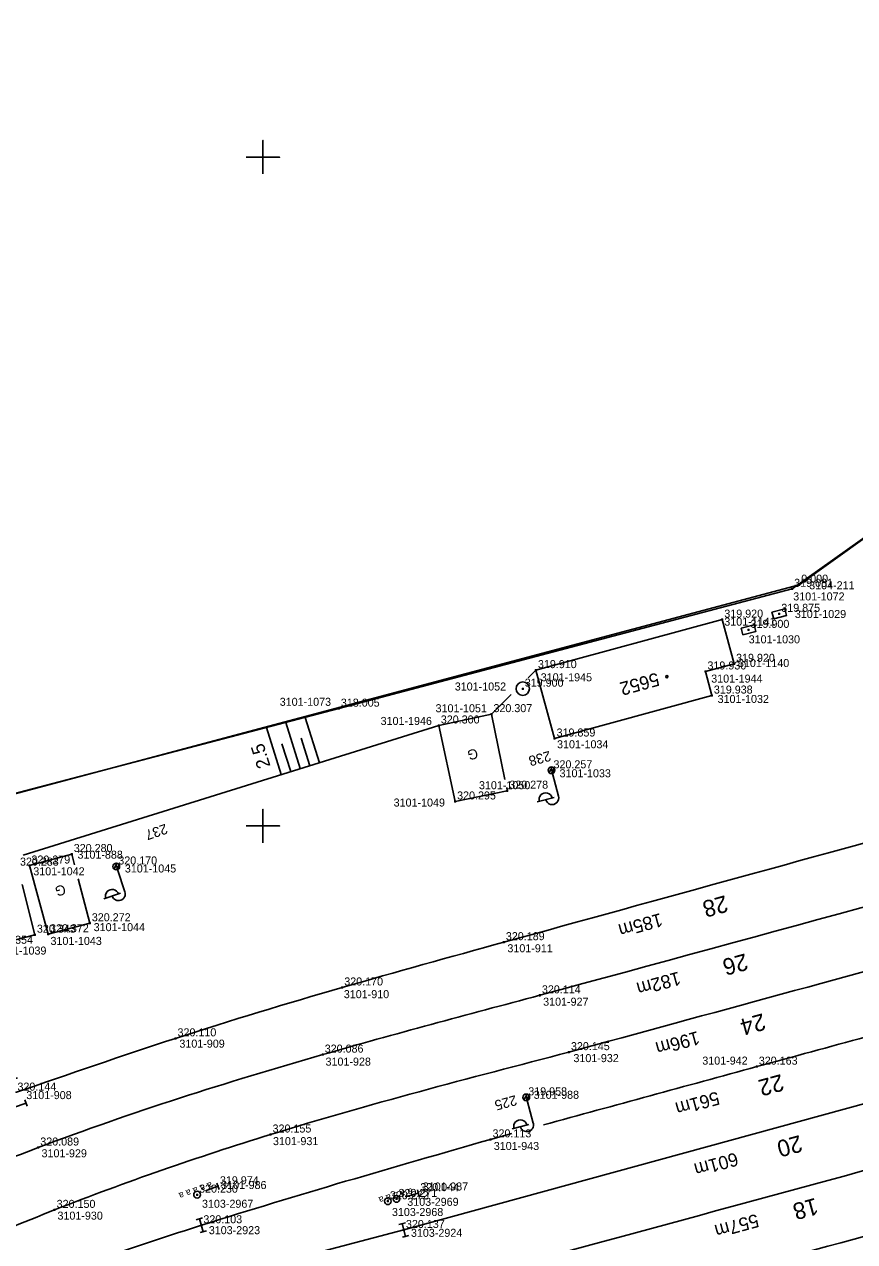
# Model space of a CAD drawing. Extents: x -821875 to -821475, y -1070280 to -1069975.
# Drawn here: x -821717.8 to -821655.7, y -1070181.1 to -1070090.1 of the extents above; entities that cross this region are included whole.
import ezdxf

# ---------------------------------------------------------------- set-up
doc = ezdxf.new("R2010")
doc.units = 0
for name, color, linetype in [('Vrstva 1', 7, 'Continuous'), ('Vrstva 15', 7, 'Continuous'), ('Vrstva 17', 7, 'Continuous'), ('Vrstva 23', 7, 'Continuous'), ('Vrstva 25', 7, 'Continuous'), ('Vrstva 28', 7, 'Continuous'), ('Vrstva 3', 7, 'Continuous'), ('Vrstva 43', 7, 'Continuous'), ('Vrstva 48', 7, 'Continuous'), ('Vrstva 49', 7, 'Continuous'), ('Vrstva 52', 7, 'Continuous'), ('Vrstva 53', 7, 'Continuous'), ('Vrstva 57', 7, 'Continuous'), ('Vrstva 59', 7, 'Continuous'), ('Vrstva 6', 7, 'Continuous'), ('Vrstva 60', 7, 'Continuous'), ('Vrstva 61', 7, 'Continuous')]:
    doc.layers.add(name, color=color, linetype=linetype)

# ---------------------------------------------------------------- blocks, each defined once
blk = doc.blocks.new('BOD')
at = {"layer": 'Vrstva 3'}
for p, q in [((-0.15, 0), (0.15, 0)), ((0, -0.15), (0, 0.15))]:
    blk.add_line(p, q, dxfattribs=at)

msp = doc.modelspace()

# ---------------------------------------------------------------- linework, layer by layer
at = {"layer": 'Vrstva 1'}
for p, q in [((-821682.909, -1070141.641), (-821682.909, -1070141.641)), ((-821681.396, -1070173.002), (-821682.977, -1070173.434))]:
    msp.add_line(p, q, dxfattribs=at)
for points in [[(-821701.25, -1070100), (-821700, -1070100), (-821700, -1070098.75), (-821700, -1070100), (-821698.75, -1070100), (-821700, -1070100), (-821700, -1070101.25)], [(-821701.25, -1070150), (-821700, -1070150), (-821700, -1070148.75), (-821700, -1070150), (-821698.75, -1070150), (-821700, -1070150), (-821700, -1070151.25)], [(-821647.71, -1070168.745), (-821689.454, -1070180.207)], [(-821689.454, -1070180.207), (-821700.898, -1070183.216)]]:
    msp.add_lwpolyline(points, dxfattribs=at)
for points in [[(-821515.135, -1070116.801), (-821528.933, -1070119.148), (-821545.007, -1070122.191), (-821565.452, -1070126.847), (-821593.911, -1070134.524), (-821616.729, -1070140.773), (-821646.681, -1070148.977), (-821681.98, -1070158.691), (-821694.065, -1070162.076), (-821706.535, -1070165.88), (-821718.507, -1070169.937)], [(-821540.596, -1070125.428), (-821552.18, -1070128.307), (-821562.458, -1070130.974), (-821571.2, -1070133.262), (-821591.887, -1070138.848), (-821628.102, -1070148.713), (-821679.285, -1070162.663)], [(-821540.784, -1070127.42), (-821561.358, -1070134.748), (-821573.215, -1070138.464), (-821586.824, -1070142.326), (-821602.341, -1070146.553), (-821645.37, -1070158.257), (-821677.113, -1070166.912)], [(-821500, -1070134.157), (-821525.227, -1070140.424), (-821545.665, -1070145.962), (-821584.89, -1070156.649), (-821608.863, -1070163.173), (-821645.742, -1070173.228), (-821684.141, -1070183.689)], [(-821500, -1070139.002), (-821505.719, -1070140.359), (-821526.796, -1070145.75), (-821547.362, -1070151.333), (-821583.687, -1070161.245), (-821611.332, -1070168.765), (-821648.899, -1070179.006), (-821680.4, -1070187.609), (-821711.133, -1070195.974)], [(-821500, -1070143.947), (-821500.602, -1070144.082), (-821526.98, -1070150.62), (-821544.477, -1070155.432), (-821558.026, -1070159.151), (-821579.135, -1070164.951), (-821610.376, -1070173.463), (-821647.463, -1070183.595), (-821678.921, -1070192.191), (-821710.276, -1070200.761)], [(-821500, -1070148.817), (-821511.77, -1070151.622), (-821530.609, -1070156.564), (-821556.604, -1070163.701), (-821576.895, -1070169.217), (-821607.294, -1070177.525), (-821643.435, -1070187.343), (-821669.656, -1070194.488)], [(-821679.285, -1070162.663), (-821695.528, -1070167.095), (-821716.799, -1070174.043), (-821730.799, -1070179.932), (-821744.379, -1070186.736), (-821755.356, -1070192.851), (-821764.427, -1070198.469)], [(-821654.889, -1070165.767), (-821663.065, -1070167.996), (-821679.008, -1070172.349)], [(-821677.113, -1070166.912), (-821699.427, -1070173.07), (-821715.575, -1070178.704), (-821729.749, -1070184.723), (-821746.361, -1070192.156), (-821759.601, -1070198.262)], [(-821682.977, -1070173.434), (-821704.603, -1070179.855), (-821714.119, -1070183.088), (-821722.706, -1070186.589), (-821730.813, -1070190.332)]]:
    msp.add_spline(points, degree=3, dxfattribs=at)
at = {"layer": 'Vrstva 15'}
msp.add_line((-821717.633, -1070170.96), (-821717.793, -1070170.487), dxfattribs=at)
msp.add_lwpolyline([(-821718.355, -1070168.83), (-821719.301, -1070169.151), (-821718.659, -1070171.044), (-821717.713, -1070170.723)], dxfattribs=at)
at = {"layer": 'Vrstva 17'}
msp.add_lwpolyline([(-821785.347, -1070191.975), (-821782.414, -1070181.46), (-821781.172, -1070177.336), (-821779.748, -1070173.57), (-821777.608, -1070170.061), (-821774.963, -1070166.997), (-821771.94, -1070164.191), (-821768.526, -1070161.97), (-821763.149, -1070159.284), (-821721.814, -1070148.42), (-821694.32, -1070141.229), (-821660.419, -1070132.27), (-821642.912, -1070119.833)], dxfattribs=at)
at = {"layer": 'Vrstva 23'}
for points in [[(-821679.583, -1070138.349), (-821665.644, -1070134.573), (-821664.764, -1070137.878), (-821666.903, -1070138.449), (-821666.425, -1070140.251), (-821678.187, -1070143.462), (-821679.583, -1070138.349)], [(-821686.846, -1070142.486), (-821682.909, -1070141.641), (-821681.898, -1070146.514)], [(-821681.77, -1070147.129), (-821681.722, -1070147.361), (-821685.626, -1070148.168), (-821686.846, -1070142.486)], [(-821717.462, -1070152.96), (-821714.296, -1070152.1), (-821714.087, -1070152.903)], [(-821713.81, -1070153.963), (-821712.945, -1070157.276), (-821716.07, -1070158.096), (-821717.462, -1070152.96)], [(-821720.377, -1070158.431), (-821720.247, -1070158.958), (-821717.052, -1070158.132), (-821717.998, -1070154.384)]]:
    msp.add_lwpolyline(points, dxfattribs=at)
at = {"layer": 'Vrstva 25'}
for p, q in [((-821678.361, -1070145.598), (-821678.597, -1070146.014)), ((-821678.207, -1070145.706), (-821678.424, -1070146.088)), ((-821678.352, -1070146.081), (-821677.886, -1070147.768)), ((-821678.224, -1070147.861), (-821679.477, -1070148.207)), ((-821710.92, -1070152.784), (-821711.132, -1070153.213)), ((-821710.76, -1070152.883), (-821710.955, -1070153.277)), ((-821710.883, -1070153.266), (-821710.321, -1070154.923)), ((-821710.653, -1070155.035), (-821711.884, -1070155.452)), ((-821680.246, -1070170.047), (-821680.484, -1070170.464)), ((-821680.093, -1070170.156), (-821680.311, -1070170.539)), ((-821680.238, -1070170.531), (-821679.776, -1070172.219)), ((-821680.113, -1070172.312), (-821681.368, -1070172.655))]:
    msp.add_line(p, q, dxfattribs=at)
for points in [[(-821661.801, -1070134.51), (-821661.929, -1070134.027), (-821660.963, -1070133.772), (-821660.835, -1070134.255), (-821661.801, -1070134.51)], [(-821664.101, -1070135.706), (-821664.229, -1070135.223), (-821663.263, -1070134.968), (-821663.135, -1070135.451), (-821664.101, -1070135.706)]]:
    msp.add_lwpolyline(points, dxfattribs=at)
for centre in [(-821678.418, -1070145.84), (-821678.418, -1070145.84), (-821710.963, -1070153.029), (-821710.963, -1070153.029), (-821680.304, -1070170.29), (-821680.304, -1070170.29)]:
    msp.add_circle(centre, 0.25, dxfattribs=at)
for centre, start, end in [((-821678.852, -1070148.028), 14.71863, 196.12377), ((-821678.368, -1070147.901), 195.4212, 15.4212), ((-821711.27, -1070155.238), 18.01661, 199.42176), ((-821710.795, -1070155.084), 198.71919, 18.71919), ((-821680.742, -1070172.477), 14.6095, 196.01465), ((-821680.258, -1070172.351), 195.31207, 15.31207)]:
    msp.add_arc(centre, 0.5, start, end, dxfattribs=at)
at = {"layer": 'Vrstva 28'}
for p, q in [((-821704.948, -1070177.567), (-821704.898, -1070177.567)), ((-821690.68, -1070178.061), (-821690.63, -1070178.061)), ((-821690.032, -1070177.888), (-821689.982, -1070177.888))]:
    msp.add_line(p, q, dxfattribs=at)
for centre in [(-821704.923, -1070177.567), (-821690.655, -1070178.061), (-821690.007, -1070177.888)]:
    msp.add_circle(centre, 0.25, dxfattribs=at)
at = {"layer": 'Vrstva 3'}
for p, q in [((-821704.505, -1070179.304), (-821704.985, -1070179.446)), ((-821704.461, -1070180.335), (-821704.745, -1070179.375)), ((-821689.339, -1070179.66), (-821689.823, -1070179.787)), ((-821689.327, -1070180.691), (-821689.581, -1070179.723)), ((-821704.221, -1070180.264), (-821704.701, -1070180.406)), ((-821689.085, -1070180.627), (-821689.569, -1070180.754))]:
    msp.add_line(p, q, dxfattribs=at)
at = {"layer": 'Vrstva 43'}
msp.add_circle((-821680.567, -1070139.735), 0.5, dxfattribs=at)
at = {"layer": 'Vrstva 48'}
for p, q in [((-821699.735, -1070142.645), (-821698.639, -1070146.162)), ((-821698.282, -1070142.265), (-821697.207, -1070145.715)), ((-821696.83, -1070141.885), (-821695.775, -1070145.269)), ((-821697.13, -1070143.442), (-821696.491, -1070145.492)), ((-821698.574, -1070143.849), (-821697.923, -1070145.939))]:
    msp.add_line(p, q, dxfattribs=at)
at = {"layer": 'Vrstva 49'}
for p, q in [((-821680.17, -1070138.93), (-821679.583, -1070138.349)), ((-821682.909, -1070141.641), (-821681.433, -1070140.18)), ((-821717.932, -1070152.175), (-821686.846, -1070142.486))]:
    msp.add_line(p, q, dxfattribs=at)
at = {"layer": 'Vrstva 52'}
msp.add_lwpolyline([(-821666.425, -1070140.251), (-821678.187, -1070143.462), (-821679.583, -1070138.349), (-821665.644, -1070134.573), (-821664.764, -1070137.878), (-821666.903, -1070138.449), (-821666.425, -1070140.251)], dxfattribs=at)
at = {"layer": 'Vrstva 53'}
msp.add_lwpolyline([(-821734.56, -1070151.86), (-821659.89, -1070131.96), (-821621.57, -1070104.56), (-821609.88, -1070096.2), (-821593.26, -1070084.26), (-821583.18, -1070077.05), (-821575.55, -1070071.56), (-821563.91, -1070063.18), (-821553.98, -1070056.16), (-821553.05, -1070055.49), (-821551.21, -1070054.16)], dxfattribs=at)
at = {"layer": 'Vrstva 59'}
msp.add_circle((-821669.792, -1070138.844), 0.0873, dxfattribs=at)
at = {"layer": 'Vrstva 6'}
for p, q in [((-821704.301, -1070177.268), (-821703.365, -1070176.942)), ((-821703.283, -1070177.178), (-821703.447, -1070176.706)), ((-821688.316, -1070177.698), (-821688.446, -1070177.216)), ((-821689.336, -1070177.716), (-821688.381, -1070177.457))]:
    msp.add_line(p, q, dxfattribs=at)

# ---------------------------------------------------------------- block references
at = {"layer": 'Vrstva 60', "xscale": 0.5, "yscale": 0.5}
for p in [(-821660.419, -1070132.27), (-821659.89, -1070131.96), (-821665.644, -1070134.573), (-821661.382, -1070134.141), (-821663.682, -1070135.337), (-821664.764, -1070137.878), (-821679.583, -1070138.349), (-821666.903, -1070138.449), (-821680.567, -1070139.735), (-821666.425, -1070140.251), (-821694.32, -1070141.229), (-821682.909, -1070141.641), (-821686.846, -1070142.486), (-821678.187, -1070143.462), (-821678.418, -1070145.84), (-821681.722, -1070147.361), (-821685.626, -1070148.168), (-821714.296, -1070152.1), (-821717.462, -1070152.96), (-821710.963, -1070153.029), (-821712.945, -1070157.276), (-821717.052, -1070158.132), (-821716.07, -1070158.096), (-821681.98, -1070158.691), (-821694.065, -1070162.076), (-821679.285, -1070162.663), (-821706.535, -1070165.88), (-821695.528, -1070167.095), (-821677.113, -1070166.912), (-821663.065, -1070167.996), (-821680.304, -1070170.29), (-821699.427, -1070173.07), (-821682.977, -1070173.434), (-821716.799, -1070174.043), (-821703.365, -1070176.942), (-821704.923, -1070177.567), (-821690.655, -1070178.061), (-821690.007, -1070177.888), (-821688.381, -1070177.457), (-821715.575, -1070178.704), (-821704.603, -1070179.855), (-821689.454, -1070180.207)]:
    msp.add_blockref('BOD', p, dxfattribs=at)

# ---------------------------------------------------------------- texts
at = {"layer": 'Vrstva 1'}
for s, height, rotation, p in [('28', 1.25, 195.40311, (-821665.428, -1070155.167)), ('185m', 1, 195.40936, (-821670.275, -1070156.502)), ('26', 1.25, 195.24604, (-821663.929, -1070159.514)), ('182m', 1, 195.24601, (-821668.915, -1070160.873)), ('24', 1.25, 195.26029, (-821662.613, -1070163.993)), ('196m', 1, 195.26183, (-821667.496, -1070165.325)), ('22', 1.25, 195.24498, (-821661.248, -1070168.537)), ('561m', 1, 195.25897, (-821666.015, -1070169.837)), ('20', 1.25, 195.25713, (-821659.863, -1070173.098)), ('601m', 1, 195.2521, (-821664.613, -1070174.394)), ('18', 1.25, 195.24444, (-821658.674, -1070177.789)), ('557m', 1, 195.2423, (-821663.079, -1070178.99))]:
    msp.add_text(s, height=height, rotation=rotation, dxfattribs=at).set_placement(p)
at = {"layer": 'Vrstva 23'}
for rotation, p in [(191.67918, (-821684.002, -1070144.201)), (194.70294, (-821714.86, -1070154.36))]:
    msp.add_text('G', height=0.75, rotation=rotation, dxfattribs=at).set_placement(p)
at = {"layer": 'Vrstva 25'}
for s, rotation, p in [('238', 195.42117, (-821678.578, -1070144.377)), ('237', 198.7192, (-821707.287, -1070149.825)), ('225', 195.3121, (-821681.122, -1070170.119))]:
    msp.add_text(s, height=0.75, rotation=rotation, dxfattribs=at).set_placement(p)
at = {"layer": 'Vrstva 48'}
msp.add_text('2.5', height=1, rotation=107.30856, dxfattribs=at).set_placement((-821699.422, -1070145.521))
at = {"layer": 'Vrstva 57'}
msp.add_text('5652', height=1, rotation=195.26954, dxfattribs=at).set_placement((-821670.52, -1070138.519))
at = {"layer": 'Vrstva 6'}
for rotation, p in [(199.20325, (-821703.529, -1070176.47)), (195.21145, (-821688.511, -1070176.974))]:
    msp.add_text('  a a a a a', height=0.5, rotation=rotation, dxfattribs=at).set_placement(p)
at = {"layer": 'Vrstva 60'}
for s, p in [('3104-211', (-821659.147, -1070132.305)), ('3101-1072', (-821660.339, -1070133.138)), ('3101-1141', (-821665.494, -1070135.023)), ('3101-1029', (-821660.22, -1070134.452)), ('3101-1030', (-821663.671, -1070136.344)), ('3101-1140', (-821664.474, -1070138.119)), ('3101-1945', (-821679.223, -1070139.183)), ('3101-1944', (-821666.474, -1070139.283)), ('3101-1052', (-821685.652, -1070139.872)), ('3101-1073', (-821698.742, -1070141.016)), ('3101-1051', (-821687.087, -1070141.498)), ('3101-1032', (-821665.996, -1070140.805)), ('3101-1946', (-821691.198, -1070142.448)), ('3101-1034', (-821678.002, -1070144.191)), ('3101-1033', (-821677.814, -1070146.36)), ('3101-1050', (-821683.841, -1070147.253)), ('3101-1049', (-821690.223, -1070148.549)), ('3101-888', (-821713.866, -1070152.446)), ('3101-1042', (-821717.173, -1070153.689)), ('3101-1045', (-821710.324, -1070153.479)), ('3101-1044', (-821712.655, -1070157.865)), ('3101-1039', (-821720.028, -1070159.617)), ('3101-1043', (-821715.885, -1070158.894)), ('3101-911', (-821681.714, -1070159.443)), ('3101-910', (-821693.95, -1070162.875)), ('3101-927', (-821679.042, -1070163.438)), ('3101-909', (-821706.245, -1070166.574)), ('3101-928', (-821695.316, -1070167.918)), ('3101-932', (-821676.778, -1070167.656)), ('3101-942', (-821667.14, -1070167.843)), ('3101-908', (-821717.694, -1070170.422)), ('3101-988', (-821679.75, -1070170.398)), ('3101-931', (-821699.246, -1070173.862)), ('3101-943', (-821682.734, -1070174.226)), ('3101-929', (-821716.555, -1070174.772)), ('3101-986', (-821703.122, -1070177.144)), ('3101-987', (-821688.044, -1070177.254)), ('3103-2967', (-821704.555, -1070178.546)), ('3103-2969', (-821689.203, -1070178.4)), ('3101-930', (-821715.363, -1070179.434)), ('3103-2968', (-821690.349, -1070179.164)), ('3103-2923', (-821704.048, -1070180.522)), ('3103-2924', (-821688.93, -1070180.719))]:
    msp.add_text(s, height=0.6, dxfattribs=at).set_placement(p)
at = {"layer": 'Vrstva 61'}
for s, p in [('319.081', (-821660.269, -1070132.12)), ('0.000', (-821659.74, -1070131.81)), ('319.875', (-821661.232, -1070133.991)), ('319.920', (-821665.494, -1070134.423)), ('319.900', (-821663.532, -1070135.187)), ('319.920', (-821664.614, -1070137.728)), ('319.910', (-821679.433, -1070138.199)), ('319.930', (-821666.753, -1070138.299)), ('319.900', (-821680.417, -1070139.585)), ('319.938', (-821666.275, -1070140.101)), ('318.005', (-821694.17, -1070141.079)), ('320.307', (-821682.759, -1070141.491)), ('320.300', (-821686.696, -1070142.336)), ('319.859', (-821678.037, -1070143.312)), ('320.257', (-821678.268, -1070145.69)), ('320.278', (-821681.572, -1070147.211)), ('320.295', (-821685.476, -1070148.018)), ('320.280', (-821714.146, -1070151.95)), ('320.283', (-821718.168, -1070152.965)), ('320.279', (-821717.312, -1070152.81)), ('320.170', (-821710.813, -1070152.879)), ('320.272', (-821712.795, -1070157.126)), ('320.354', (-821720.097, -1070158.808)), ('320.343', (-821716.902, -1070157.982)), ('320.372', (-821715.92, -1070157.946)), ('320.189', (-821681.83, -1070158.541)), ('320.170', (-821693.915, -1070161.926)), ('320.114', (-821679.135, -1070162.513)), ('320.110', (-821706.385, -1070165.73)), ('320.086', (-821695.378, -1070166.945)), ('320.145', (-821676.963, -1070166.762)), ('320.163', (-821662.915, -1070167.846)), ('320.144', (-821718.357, -1070169.787)), ('319.958', (-821680.154, -1070170.14)), ('320.155', (-821699.277, -1070172.92)), ('320.113', (-821682.827, -1070173.284)), ('320.089', (-821716.649, -1070173.893)), ('319.974', (-821703.215, -1070176.792)), ('320.230', (-821704.773, -1070177.417)), ('320.272', (-821690.505, -1070177.911)), ('320.271', (-821689.857, -1070177.738)), ('320.044', (-821688.231, -1070177.307)), ('320.150', (-821715.425, -1070178.554)), ('320.103', (-821704.453, -1070179.705)), ('320.137', (-821689.304, -1070180.057))]:
    msp.add_text(s, height=0.6, dxfattribs=at).set_placement(p)

doc.saveas('drawing.dxf')
